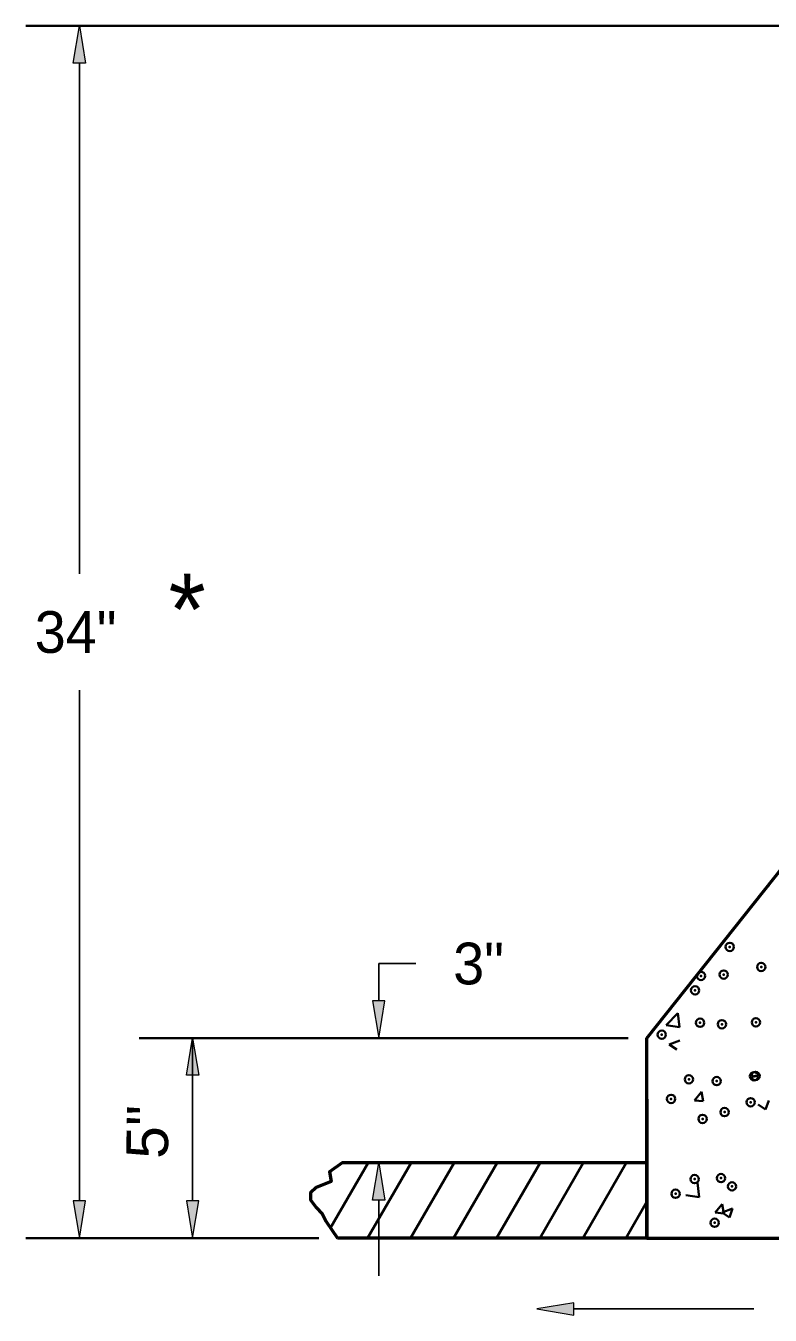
# Model space of a CAD drawing. Extents: x 14 to 49.3, y 28 to 50.
# Drawn here: x 32.455 to 34.953, y 36.623 to 40.948 of the extents above; entities that cross this region are included whole.
import ezdxf

# ---------------------------------------------------------------- set-up
doc = ezdxf.new("R2010")
doc.units = 0
doc.header["$LTSCALE"] = 0.056
doc.header["$PDMODE"] = 32
doc.header["$PDSIZE"] = 0.028
for name, color, linetype, lineweight in [('1', 7, 'Continuous', 35), ('3', 7, 'Continuous', 13), ('6', 7, 'Continuous', 13)]:
    doc.layers.add(name, color=color, linetype=linetype, lineweight=lineweight)

msp = doc.modelspace()

# ---------------------------------------------------------------- hatches: boundary and pattern name
at = {"layer": '1'}
for points in [[(32.65542, 40.82292), (32.61375, 40.82292), (32.63458, 40.94792), (32.63458, 40.94792)], [(33.65975, 37.678), (33.61808, 37.678), (33.63892, 37.553), (33.63892, 37.553)], [(33.03542, 37.428), (32.99375, 37.428), (33.01458, 37.553), (33.01458, 37.553)], [(33.65975, 37.009), (33.61808, 37.009), (33.63892, 37.134), (33.63892, 37.134)], [(32.65542, 37.00658), (32.61375, 37.00658), (32.63458, 36.88158), (32.63458, 36.88158)], [(33.03542, 37.00658), (32.99375, 37.00658), (33.01458, 36.88158), (33.01458, 36.88158)]]:
    msp.add_hatch(color=256, dxfattribs=at).paths.add_polyline_path(points)
at = {"layer": '3'}
msp.add_hatch(color=256, dxfattribs=at).paths.add_polyline_path([(34.29433, 36.6235), (34.29433, 36.66525), (34.16933, 36.64442), (34.16933, 36.64442)])

# ---------------------------------------------------------------- linework, layer by layer
at = {"layer": '1'}
for p, q in [((35.63342, 40.94792), (32.45458, 40.94792)), ((34.94333, 38.06217), (34.94817, 38.06175)), ((34.94825, 38.06175), (34.94725, 38.06708)), ((34.60358, 37.59625), (34.64258, 37.63683)), ((34.64808, 37.58933), (34.64258, 37.63683)), ((34.60358, 37.59625), (34.64808, 37.58942)), ((34.47642, 37.553), (32.83458, 37.553)), ((34.61425, 37.53175), (34.64925, 37.54517)), ((34.61425, 37.53175), (34.63917, 37.515)), ((34.69842, 37.34358), (34.72258, 37.37225)), ((34.72833, 37.34092), (34.72258, 37.37225)), ((34.69842, 37.34358), (34.72833, 37.34092)), ((34.91275, 37.33042), (34.93758, 37.31367)), ((34.93758, 37.31367), (34.94775, 37.34383)), ((34.93758, 37.31367), (34.94775, 37.34383)), ((34.71433, 37.01958), (34.70883, 37.067)), ((34.66992, 37.0265), (34.71433, 37.01958)), ((34.76783, 36.96742), (34.79192, 36.99617)), ((34.79108, 36.96783), (34.82608, 36.98133)), ((34.79767, 36.96483), (34.79192, 36.99617)), ((34.81592, 36.95108), (34.82608, 36.98133)), ((34.76783, 36.96742), (34.79767, 36.96483)), ((34.79108, 36.96783), (34.81592, 36.95108)), ((33.43783, 36.88158), (32.45458, 36.88158)), ((33.43783, 36.88158), (32.83458, 36.88158))]:
    msp.add_line(p, q, dxfattribs=at)
at = {"layer": '1', "lineweight": 25}
for p, q in [((32.63458, 40.82292), (32.63458, 39.10975)), ((32.63458, 37.00658), (32.63458, 38.71975)), ((33.63892, 37.678), (33.63892, 37.803)), ((33.63892, 37.803), (33.76392, 37.803)), ((33.01458, 37.00658), (33.01458, 37.553)), ((33.63892, 37.009), (33.63892, 36.75583))]:
    msp.add_line(p, q, dxfattribs=at)
at = {"layer": '1', "lineweight": 53}
for p, q in [((34.53892, 37.553), (35.13542, 38.30408)), ((34.53892, 36.88158), (34.53892, 37.553)), ((34.53892, 36.88158), (33.50033, 36.88158))]:
    msp.add_line(p, q, dxfattribs=at)
at = {"layer": '1', "lineweight": 13}
for p, q in [((33.67817, 37.553), (33.81892, 37.553)), ((33.69675, 37.134), (33.81892, 37.134))]:
    msp.add_line(p, q, dxfattribs=at)
at = {"layer": '1', "lineweight": 40}
for p, q in [((33.47733, 36.916), (33.60325, 37.134)), ((33.60175, 36.88158), (33.74758, 37.134)), ((33.74608, 36.88158), (33.89192, 37.134)), ((33.89042, 36.88158), (34.03625, 37.134)), ((34.03475, 36.88158), (34.18058, 37.134)), ((34.17917, 36.88158), (34.32492, 37.134)), ((34.3235, 36.88158), (34.46925, 37.134)), ((34.46783, 36.88158), (34.53892, 37.00467))]:
    msp.add_line(p, q, dxfattribs=at)
at = {"layer": '1', "lineweight": 13}
for points in [[(32.65542, 40.82292), (32.61375, 40.82292), (32.63458, 40.94792), (32.63458, 40.94792)], [(33.65975, 37.678), (33.61808, 37.678), (33.63892, 37.553), (33.63892, 37.553)], [(33.03542, 37.428), (32.99375, 37.428), (33.01458, 37.553), (33.01458, 37.553)], [(33.65975, 37.009), (33.61808, 37.009), (33.63892, 37.134), (33.63892, 37.134)], [(32.65542, 37.00658), (32.61375, 37.00658), (32.63458, 36.88158), (32.63458, 36.88158)], [(33.03542, 37.00658), (32.99375, 37.00658), (33.01458, 36.88158), (33.01458, 36.88158)]]:
    msp.add_lwpolyline(points, close=True, dxfattribs=at)
at = {"layer": '1', "lineweight": 53}
for points in [[(34.53892, 37.34817), (34.53892, 36.88158), (38.0315, 36.88158), (38.0315, 37.10067)], [(34.53892, 37.134), (33.51608, 37.134), (33.47417, 37.10475), (33.47975, 37.07242), (33.4295, 37.05192), (33.40992, 37.03433), (33.40992, 37.01083), (33.4295, 36.9845), (33.449, 36.96392), (33.463, 36.93758), (33.50033, 36.88158)]]:
    msp.add_lwpolyline(points, dxfattribs=at)
at = {"layer": '1'}
for p in [(34.81717, 37.85858), (34.92258, 37.79142), (34.7205, 37.76142), (34.79675, 37.76583), (34.70067, 37.713), (34.71767, 37.60442), (34.79067, 37.59942), (34.90475, 37.60575), (34.58892, 37.56425), (34.68, 37.41467), (34.77317, 37.40858), (34.89833, 37.42508), (34.90383, 37.42575), (34.62033, 37.34892), (34.88725, 37.33767), (34.72575, 37.28175), (34.79983, 37.30483), (34.69917, 37.07983), (34.78775, 37.0835), (34.82467, 37.05558), (34.63525, 37.03067), (34.76642, 36.93367)]:
    msp.add_point(p, dxfattribs=at)
at = {"layer": '3', "lineweight": 25}
msp.add_line((34.29433, 36.64442), (34.89817, 36.64442), dxfattribs=at)
at = {"layer": '3'}
msp.add_lwpolyline([(34.29433, 36.6235), (34.29433, 36.66525), (34.16933, 36.64442), (34.16933, 36.64442)], close=True, dxfattribs=at)
at = {"layer": '6'}
for p, q in [((32.63458, 40.94792), (32.63467, 40.94792)), ((33.01458, 37.553), (33.01467, 37.553)), ((33.61567, 37.553), (33.61575, 37.553)), ((33.63892, 37.553), (33.639, 37.553)), ((34.53892, 37.553), (34.539, 37.553)), ((33.63425, 37.134), (33.63433, 37.134))]:
    msp.add_line(p, q, dxfattribs=at)
at = {"layer": '6', "lineweight": 53}
msp.add_line((33.50033, 36.88158), (33.50042, 36.88158), dxfattribs=at)
msp.add_line((33.50033, 36.88158), (33.50042, 36.88158), dxfattribs=at)

# ---------------------------------------------------------------- texts
at = {"layer": '1'}
for s, p in [('34"', (32.48458, 38.84475)), ('3"', (33.88892, 37.733))]:
    msp.add_text(s, height=0.14, dxfattribs=at).set_placement(p)
at = {"layer": '1', "width": 1.05}
msp.add_text('5"', height=0.14, rotation=88.945, dxfattribs=at).set_placement((32.93125, 37.14725))
at = {"layer": '3'}
msp.add_text('*', height=0.24, dxfattribs=at).set_placement((32.93375, 38.8705))

doc.saveas('drawing.dxf')
